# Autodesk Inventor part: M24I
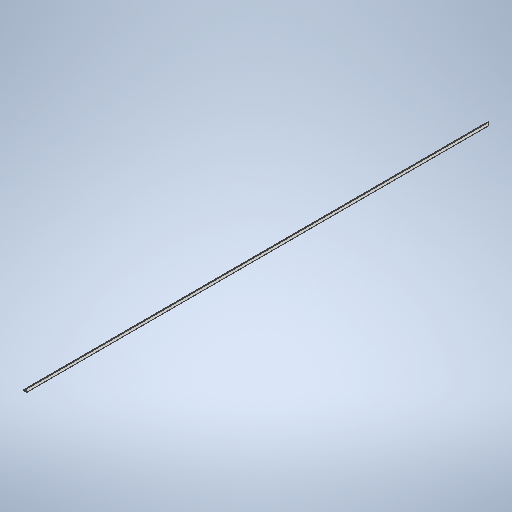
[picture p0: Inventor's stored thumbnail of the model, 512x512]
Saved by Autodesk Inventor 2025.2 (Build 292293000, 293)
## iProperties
Created: 2025-02
Part Number: M24I
Material: Générique
Document SubType Name: Sheet Metal
Designer: jonathan.arredondolo
Density: 1 g/cm^3
Sheet Metal Rule: Default_mm
Appearance: Par défaut
Author: jonathan.arredondolo
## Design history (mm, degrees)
sketch "Esquisse1"
  geometry: L1 (0, 0)-(12.058, 0); L2 (12.491, 0.276)-(21.805, 20.249); L3 (21.908, 20.171)-(12.572, 0.149); L4 (12.139, -0.127)-(0, -0.127); L5 (0, 0)-(0, 0.478); L6 (0, 0.478)-(11.754, 0.478); L7 (12.187, 0.753)-(21.372, 20.451); L8 (22.341, 19.969)-(12.876, -0.329); L9 (12.443, -0.605)-(0, -0.605); L10 (0, -0.127)-(0, -0.605); L11 (25.4, 19.558)-(25.4, -0.064); L12 (24.318, -0.064)-(24.318, 19.531); L13 (24.795, 19.531)-(24.795, -0.064); L14 (24.922, -0.064)-(24.922, 19.558); A1 r 0.478 centre (11.754, 0.955) between (11.754, 0.478) and (12.187, 0.753); A2 r 0.478 centre (12.058, 0.478) between (12.058, 0) and (12.491, 0.276); A3 r 0.478 centre (12.139, 0.351) between (12.139, -0.127) and (12.572, 0.149); A4 r 0.478 centre (12.443, -0.127) between (12.443, -0.605) and (12.876, -0.329); A5 r 2.113 centre (23.287, 19.558) between (25.4, 19.558) and (21.372, 20.451); A6 r 0.541 centre (24.859, -0.064) between (24.318, -0.064) and (25.4, -0.064); A7 r 1.514 centre (23.281, 19.531) between (24.795, 19.531) and (21.908, 20.171); A8 r 0.063 centre (24.859, -0.064) between (24.795, -0.064) and (24.922, -0.064); A9 r 1.037 centre (23.281, 19.531) between (24.318, 19.531) and (22.341, 19.969); A10 r 1.636 centre (23.287, 19.558) between (24.922, 19.558) and (21.805, 20.249); 18 further points
  constraints: 28 end point, 27 point on circle, 20 tangent, 10 centre point, 6 vertical, 4 parallel, 3 equal radius, 3 midpoint, 2 horizontal, 1 coincident, 1 horizontal alignment, 1 perpendicular, 1 vertical alignment
  dimensions: "d0" = 0.47752 distance between parallel lines of L1 L6; "d3" = 0.47752 distance between parallel lines of L9 L4; "d4" = 0.127 distance between parallel lines of L4 L1; "d6" = 0.47752 distance between parallel lines of L2 L7 (= d0); "d7" = 0.47752 distance between parallel lines of L8 L3 (= d3); "d13" = 0.47752 distance of point (24.859, -0.605) point (24.859, -0.127); "d14" = 0.47752 distance between parallel lines of L11 L14 (= d0); "d16" = 12.7 horizontal distance of point (12.7, -0.53) point (0, -0.366); "d18" = 0.47752 distance of point (23.609, 21.009) point (23.505, 20.543); "d19" = 0.47752 radius of A4; "d21" = 0.127 distance between parallel lines of L14 L13 (derived); "d22" = 22.225 vertical distance of point (24.859, -0.605) point (23.744, 21.62); "d23" = 0.127 distance between parallel lines of L3 L2 (derived); "d25" = 25.4 distance from line of L11 point (0, -0.366); "d26" = 25 deg angle of L12 L8; "d27" = 0.47752 distance of point (23.744, 21.62) point (23.641, 21.154); "d30" = 0.14491 vertical distance of point (23.609, 21.009) point (23.641, 21.154)
extrude "Extrusion1" new body sketch "Esquisse1" distance "d28" = 3048; taper "d29" = 0 deg
node "Solide1"
other parameters: "Epaisseur" = 0.5, "RayonPli" = 0.5 (= Epaisseur), "LargeurGrugeage" = 0.5 (= Epaisseur), "ProfondeurGrugeage" = 0.25 (= 0.5 x Epaisseur), "TailleGrugeage" = 2 (= 4 x Epaisseur), "SeamGap" = 0.01, "RestesMinimum" = 1 (= 2 x Epaisseur), "Rayondetransition" = 0.5 (= RayonPli), "TailleRayonJacobi" = 0.5 (= RayonPli), "TailleJeu" = 0.5 (= Epaisseur)
